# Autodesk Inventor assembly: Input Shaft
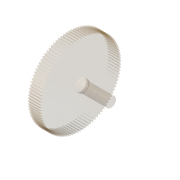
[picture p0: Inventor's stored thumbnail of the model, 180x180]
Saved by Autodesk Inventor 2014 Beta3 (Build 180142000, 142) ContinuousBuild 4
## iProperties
Created: 2011-01
Part Number: Input Shaft
Document SubType Name: Assembly
Designer: Beta-8540w
ClientObjectVersion: 1
Author: Beta-8540w
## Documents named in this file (2)
- C:\Inventor 2014 Essentials\Assemblies\Chapter 09\Design Accelerators\Shaft c09-06.iam
- C:\Inventor 2014 Essentials\Assemblies\Chapter 09\Design Accelerators\Shaft c09-04.ipt
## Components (1 placed, 1 different names)
1. Input Shaft:1
